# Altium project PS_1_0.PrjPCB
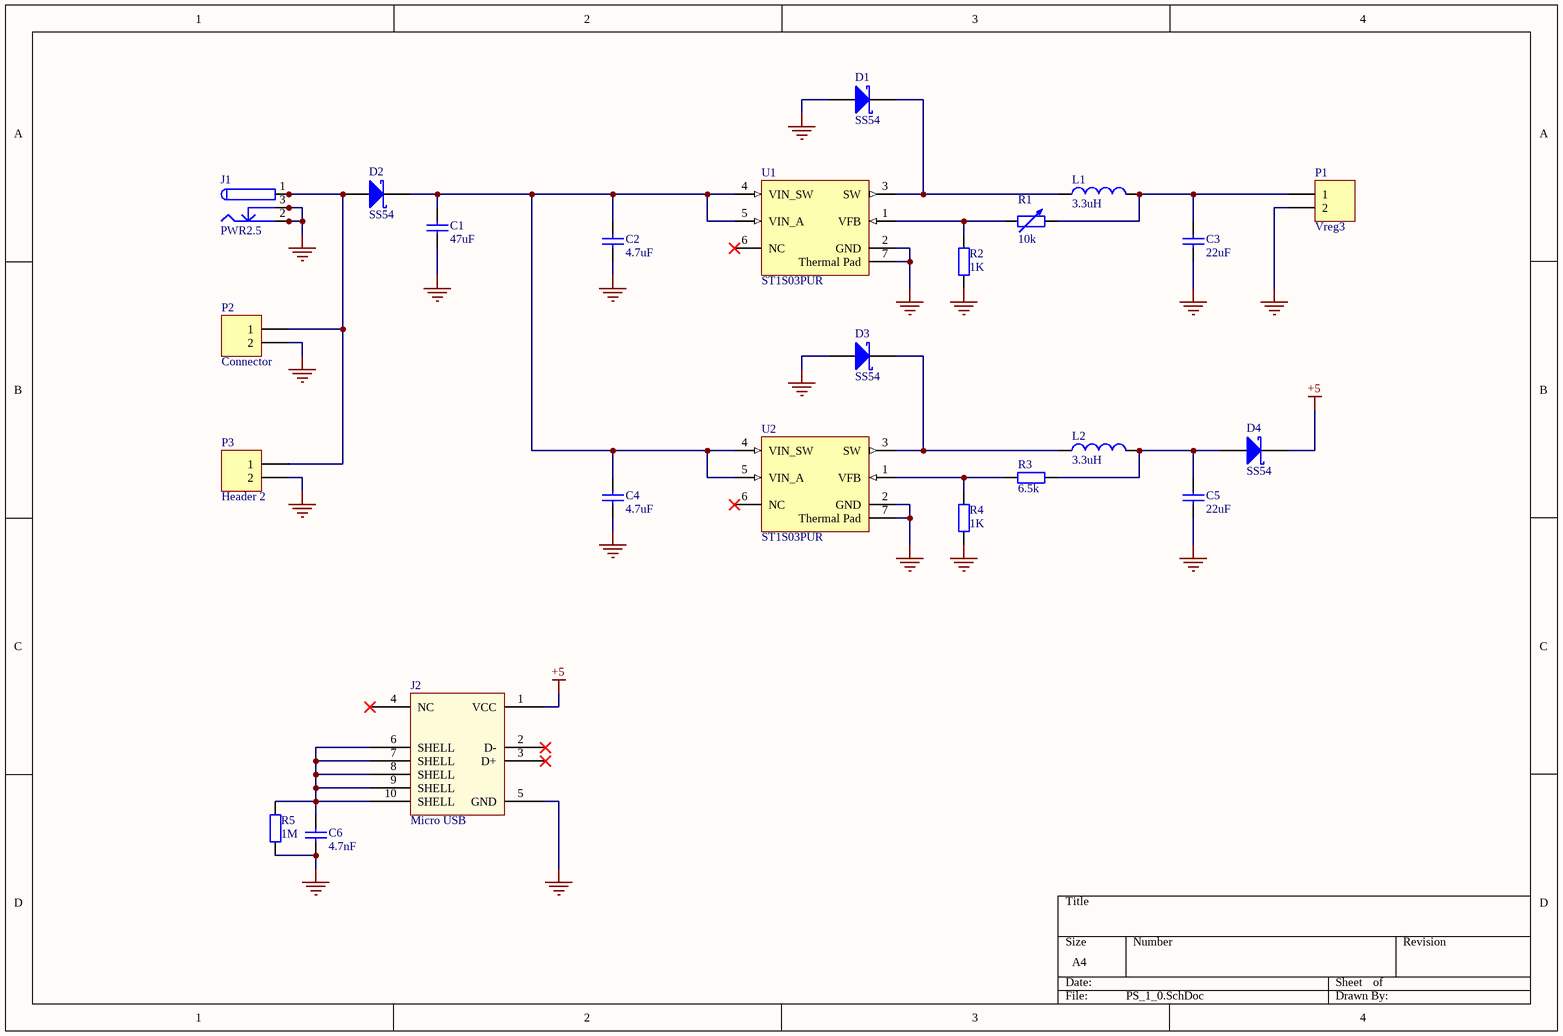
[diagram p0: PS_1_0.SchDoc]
2 sheets, 39 parts. Net scope: global (net labels, ports and power ports of the same name join across sheets).
Sheets:
  PS_1_0.SchDoc
  PS_1_0_s2.SchDoc

## Sheet PS_1_0.SchDoc
size A4

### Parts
C1  47uF  [C0805]
C2  4.7uF  [C0805]
C3  22uF  [C0805]
C4  4.7uF  [C0805]
C5  22uF  [C0805]
C6  4.7nF  [0603]
D1  SS54  [SMB]
D2  SS54  [SMB]
D3  SS54  [SMB]
D4  SS54  [SMB]
J1  PWR2.5  [KLD-0202]
J2  Micro USB
L1  3.3uH  [0402-A]
L2  3.3uH  [0402-A]
P1  Vreg3  [HDR1X2]
P2  Connector  [L_ZAC]
P3  Header 2  [HDR1X2]
R1  10k  [AXIAL-0.6]
R2  1K  [0603]
R3  6.5k  [0603]
R4  1K  [0603]
R5  1M  [0603]
U1  ST1S03PUR  [DFN6D_M]
U2  ST1S03PUR  [DFN6D_M]

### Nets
+5: D4.2(K) J2.1(VCC)
GND: C1.2 C2.2 C3.2 C4.2 C5.2 C6.2 D1.1(A) D3.1(A) J1.2 J1.2A J1.2B J1.3 J1.3A J1.3B J2.5(GND) P1.2 P2.2 P3.2 R2.1 R4.1 R5.1 U1.2(GND) U1.7(Thermal_Pad) U2.2(GND) U2.7(Thermal_Pad)
NetC1_1: C1.1 C2.1 C4.1 D2.2(K) U1.4(VIN_SW) U1.5(VIN_A) U2.4(VIN_SW) U2.5(VIN_A)
NetC3_1: C3.1 L1.2 P1.1 R1.2
NetC5_1: C5.1 D4.1(A) L2.2 R3.1
NetC6_1: C6.1 J2.6(SHELL) J2.7(SHELL) J2.8(SHELL) J2.9(SHELL) J2.10(SHELL) R5.2
NetD1_2: D1.2(K) L1.1 U1.3(SW)
NetD2_1: D2.1(A) J1.1 J1.1A J1.1B P2.1 P3.1
NetD3_2: D3.2(K) L2.1 U2.3(SW)
NetR1_1: R1.1 R2.2 U1.1(VFB)
NetR3_2: R3.2 R4.2 U2.1(VFB)

Not connected (* = marked no-connect by the designer): J2 2(D-)* 3(D+)* 4(NC)*; U1 6(NC)*; U2 6(NC)*

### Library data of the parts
C1-C6 = Cap Semi: Capacitor (Semiconductor SIM Model)
D1-D4 = D Schottky: Schottky Diode
J1 = PWR2.5: Low Voltage Power Supply Connector
J2 = Micro USB: type B
L1 L2 = Inductor: Code_IEC: 1005
P1-P3 = Header 2: Header, 2-Pin
R1 = Res Adj2: Variable Resistor; Set Position: 0.5
R2-R5 = Res2: Resistor
U1 U2 = ST1S03PUR: 1.5 A, 1.5 MHz adjustable, step-down switching regulator, DFN6D

## Sheet PS_1_0_s2.SchDoc
size A4
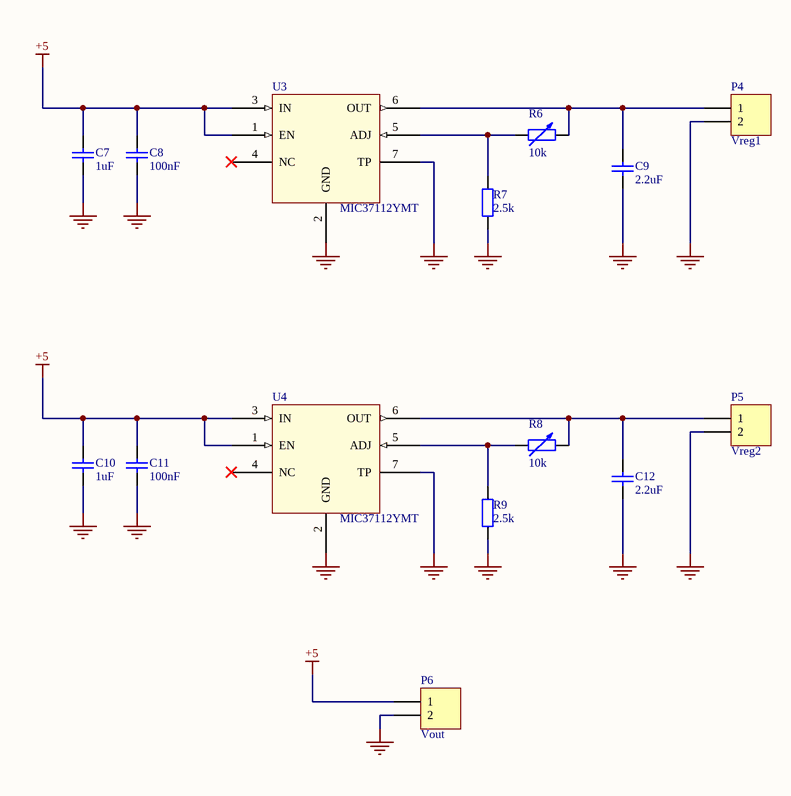
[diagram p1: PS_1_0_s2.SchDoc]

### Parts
C7  1uF  [0603]
C8  100nF  [0603]
C9  2.2uF  [0603]
C10  1uF  [0603]
C11  100nF  [0603]
C12  2.2uF  [0603]
P4  Vreg1  [HDR1X2]
P5  Vreg2  [HDR1X2]
P6  Vout  [HDR1X2]
R6  10k  [AXIAL-0.6]
R7  2.5k  [0603]
R8  10k  [AXIAL-0.6]
R9  2.5k  [0603]
U3  MIC37112YMT  [MLF6]
U4  MIC37112YMT  [MLF6]

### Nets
+5: C7.1 C8.1 C10.1 C11.1 P6.1 U3.1(EN) U3.3(IN) U4.1(EN) U4.3(IN)
GND: C7.2 C8.2 C9.2 C10.2 C11.2 C12.2 P4.2 P5.2 P6.2 R7.1 R9.1 U3.2(GND) U3.7(TP) U4.2(GND) U4.7(TP)
NetC9_1: C9.1 P4.1 R6.2 U3.6(OUT)
NetC12_1: C12.1 P5.1 R8.2 U4.6(OUT)
NetR6_1: R6.1 R7.2 U3.5(ADJ)
NetR8_1: R8.1 R9.2 U4.5(ADJ)

Not connected (* = marked no-connect by the designer): U3 4(NC)*; U4 4(NC)*

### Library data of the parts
C7-C12 = Cap Semi: Capacitor (Semiconductor SIM Model)
P4-P6 = Header 2: Header, 2-Pin
R6 R8 = Res Adj2: Variable Resistor; Set Position: 0.5
R7 R9 = Res2: Resistor
U3 U4 = MIC37112YMT: LDO, 1A

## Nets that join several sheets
+5: PS_1_0 (D4.2 J2.1), PS_1_0_s2 (9 pins)
GND: PS_1_0 (25 pins), PS_1_0_s2 (15 pins)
